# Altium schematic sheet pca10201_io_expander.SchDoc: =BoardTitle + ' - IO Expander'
size A3; Organization: Nordic Semiconductor; DocumentNumber: 5; SheetNumber: 5; SheetTotal: 10; CompanyName: Nordic Semiconductor; DocumentSize: A3
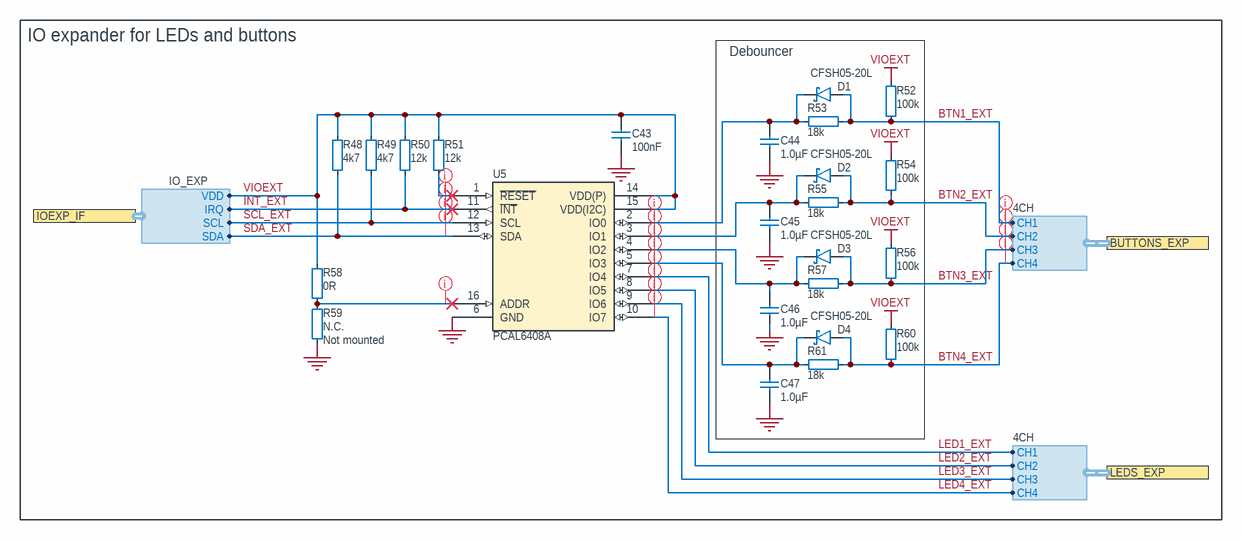
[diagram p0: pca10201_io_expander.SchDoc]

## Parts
C43  100nF  [CAPC0603X03L_C]
C44  1.0µF  [CAPC0603X03L_C]
C45  1.0µF  [CAPC0603X03L_C]
C46  1.0µF  [CAPC0603X03L_C]
C47  1.0µF  [CAPC0603X03L_C]
D1  CFSH05-20L  [SODFL35X40-2N]
D2  CFSH05-20L  [SODFL35X40-2N]
D3  CFSH05-20L  [SODFL35X40-2N]
D4  CFSH05-20L  [SODFL35X40-2N]
R48  4k7  [RESC0603X03L_C]
R49  4k7  [RESC0603X03L_C]
R50  12k  [RESC0603X03L_C]
R51  12k  [RESC0603X03L_C]
R52  100k  [RESC0603X03L_C]
R53  18k  [RESC0603X03L_C]
R54  100k  [RESC0603X03L_C]
R55  18k  [RESC0603X03L_C]
R56  100k  [RESC0603X03L_C]
R57  18k  [RESC0603X03L_C]
R58  0R  [RESC0603X03L_C]
R59  N.C.  Assembly: Not mounted  [RESC0603X03L_C_NC]
R60  100k  [RESC0603X03L_C]
R61  18k  [RESC0603X03L_C]
U5  PCAL6408A  [XQFN40P180X260X50-16N]

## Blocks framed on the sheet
IO expander for LEDs and buttons: C43 R48-R51 R58 R59 U5
Debouncer: C44-C47 D1-D4 R52-R57 R60 R61

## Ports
BUTTONS_EXP (harness 4CH), IOEXP_IF (harness IO_EXP), LEDS_EXP (harness 4CH)

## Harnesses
IO_EXP: VDD, SCL, SDA, IRQ
4CH: CH1, CH2, CH3, CH4

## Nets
GND: C43.1 C44.2 C45.1 C46.1 C47.1 R59.1 U5.6(GND)
VIOEXT: C43.2 R48.2 R49.2 R50.2 R51.2 R52.2 R54.2 R56.2 R58.2 R60.2 U5.14(VDD(P)) U5.15(VDD(I2C)) ; port IOEXP_IF.VDD
BTN1_EXT: D1.1(A) R52.1 R53.2 ; port BUTTONS_EXP.CH1
BTN2_EXT: D2.1(A) R54.1 R55.2 ; port BUTTONS_EXP.CH2
BTN3_EXT: D3.1(A) R56.1 R57.2 ; port BUTTONS_EXP.CH3
BTN4_EXT: D4.1(A) R60.1 R61.2 ; port BUTTONS_EXP.CH4
INT_EXT: R50.1 U5.11(~{INT}) ; port IOEXP_IF.IRQ
LED1_EXT: U5.7(IO4) ; port LEDS_EXP.CH1
LED2_EXT: U5.8(IO5) ; port LEDS_EXP.CH2
LED3_EXT: U5.9(IO6) ; port LEDS_EXP.CH3
LED4_EXT: U5.10(IO7) ; port LEDS_EXP.CH4
SCL_EXT: R49.1 U5.12(SCL) ; port IOEXP_IF.SCL
SDA_EXT: R48.1 U5.13(SDA) ; port IOEXP_IF.SDA
NetC44_1: C44.1 D1.3(C) R53.1 U5.2(IO0)
NetC45_2: C45.2 D2.3(C) R55.1 U5.3(IO1)
NetC46_2: C46.2 D3.3(C) R57.1 U5.4(IO2)
NetC47_2: C47.2 D4.3(C) R61.1 U5.5(IO3)
NetR51_1: R51.1 U5.1(~{RESET})
NetR58_1: R58.1 R59.2 U5.16(ADDR)

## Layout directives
net class GPIO: BTN1_EXT, BTN2_EXT, BTN3_EXT, BTN4_EXT, INT_EXT, LED1_EXT, LED2_EXT, LED3_EXT, LED4_EXT, NetC44_1, NetC45_2, NetC46_2, NetC47_2, NetR51_1, NetR58_1, SCL_EXT, SDA_EXT

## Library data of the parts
C43 = C0201-100n: Capacitor, X5R, ±10%, 100nF, 16V; Manufacturer: N.A.; Part number IPS: 00000001248, 00000002505; Part number Norautron: 262071862; Part number NEMS: 100200078; Pad Count: 2; Component Status: Active
C44-C47 = C0201-1µ0: Capacitor, X5R, ±10%; Manufacturer: N.A.; Part number IPS: 00000001723; Part number NEMS: 100200084; Note: 10V; Pad Count: 2; Component Status: Active
D1-D4 = CFSH05-20L: DIODE SCHOTTKY 20V 500MA SOD882; Manufacturer: Central Semiconductor Corp.; Part number IPS: 00000002493; Part number NEMS: 101300101; Note: N.A.; Pad Count: 2; Component Status: Active
R48 R49 = R0201-4k7: Resistor, ±1%, 0.05W; Manufacturer: N.A.; Part number IPS: 00000001706; Part number NEMS: 100100061; Note: Chip Res 1%; Pad Count: 2; Component Status: Active
R50 R51 = R0201-12k: Resistor, ±1%, 0.05W; Manufacturer: N.A.; Part number IPS: 00000007891; Part number Norautron: 26192279; Part number NEMS: 100100066; Note: Chip Res 1%; Pad Count: 2; Component Status: Active
R52 R54 R56 R60 = R0201-100k: Resistor, ±1%, 0.05W; Manufacturer: N.A.; Part number IPS: 00000001419; Part number Norautron: 26108487; Part number NEMS: 100100080; Note: Chip Res 1%; Pad Count: 2; Component Status: Active
R53 R55 R57 R61 = R0201-18k: Resistor, ±1%, 0.05W; Manufacturer: N.A.; Part number IPS: 00000001707; Part number NEMS: 100100069; Note: Chip Res 1%; Pad Count: 2; Component Status: Active
R58 = R0201-0R: Resistor, ±5%, 0.05W; Manufacturer: N.A.; Part number IPS: 00000003245; Part number NEMS: 100100001; Note: Chip Res 5%; Pad Count: 2; Component Status: Active
R59 = R0201-N.C.: Not mounted; Manufacturer: N.A.; Part number NEMS: 100100107; Note: Chip Res; Pad Count: 2; Component Status: Active
U5 = PCAL6408AHK: 8-bit I2C-bus I/O expander with interrupt output; Manufacturer: NXP Semiconductors; Part number IPS: 00000009987; Part number NEMS: 101900289; Note: N.A.; Artikkelnr Noca: 15079321; Pad Count: 16; Component Status: Active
